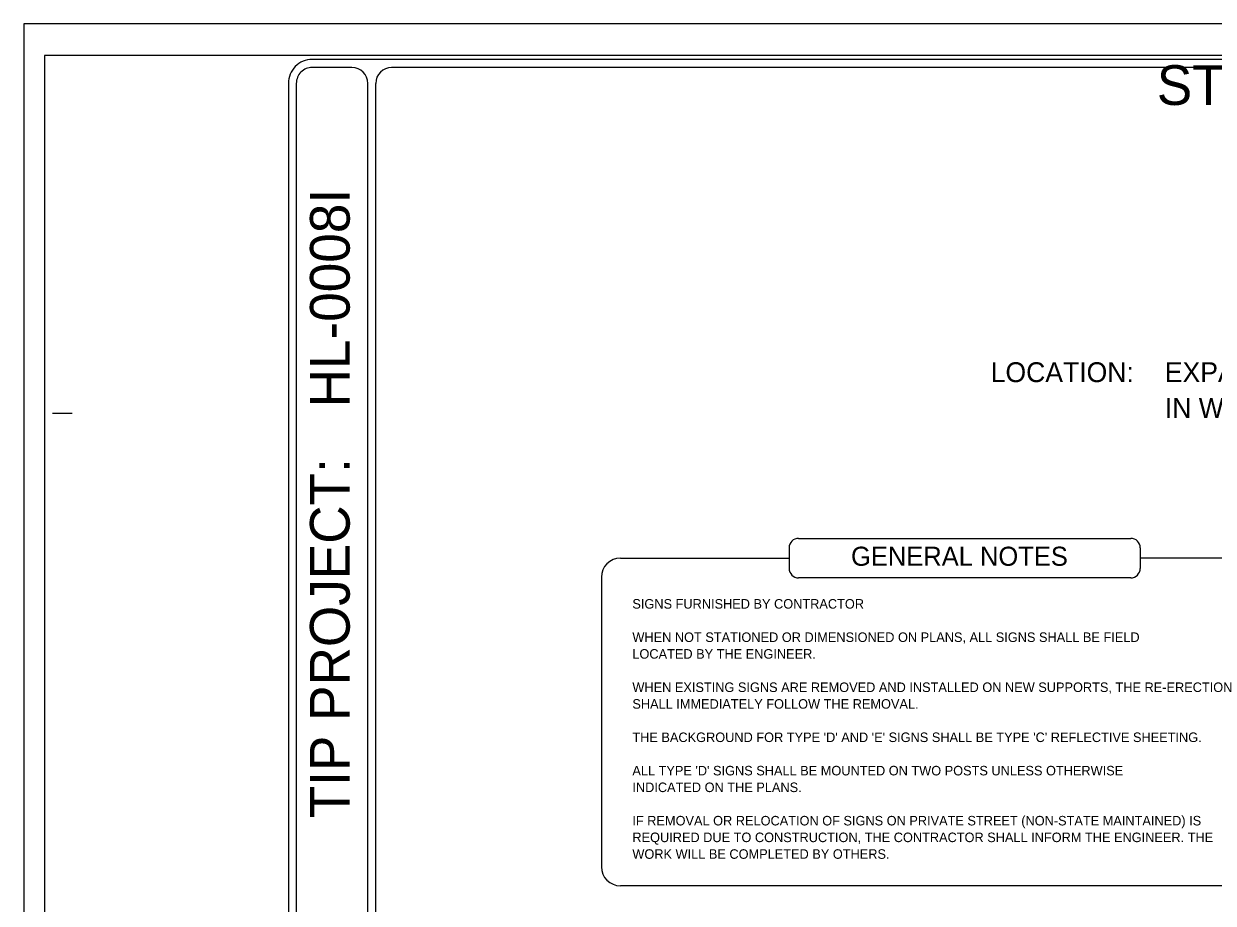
# Model space of a CAD drawing. Extents: x 2046816 to 2049224, y 578750 to 586986.
# Drawn here: x 2047541 to 2048289, y 586432 to 586986 of the extents above; entities that cross this region are included whole.
import ezdxf

# ---------------------------------------------------------------- set-up
doc = ezdxf.new("R2010")
doc.units = 0
for name, color, linetype in [('Default', 7, 'Continuous'), ('Sheet Data Field CELL', 7, 'Continuous'), ('Sheet Plot Border Inside CELL', 7, 'Continuous'), ('Sheet Plot Border Outside CELL', 7, 'Continuous'), ('Sheet Title CELL', 7, 'Continuous')]:
    doc.layers.add(name, color=color, linetype=linetype)

msp = doc.modelspace()

# ---------------------------------------------------------------- linework, layer by layer
at = {"layer": 'Sheet Plot Border Inside CELL'}
msp.add_lwpolyline([(2047553.67, 585910.81), (2049219.66, 585910.81), (2049219.66, 586965.81), (2047553.67, 586965.81)], close=True, dxfattribs=at)
at = {"layer": 'Sheet Plot Border Outside CELL'}
msp.add_lwpolyline([(2049224.17, 586985.81), (2047540.67, 586985.81), (2047540.67, 585890.81), (2049224.17, 585890.81)], close=True, dxfattribs=at)
at = {"layer": 'Sheet Title CELL'}
for p, q in [((2047757.16, 585928.33), (2047757.16, 586948.31)), ((2047762.16, 585928.31), (2047762.16, 586948.31)), ((2047558.66, 586740.81), (2047571.16, 586740.81)), ((2048028.31, 586661.97), (2048237.28, 586661.97)), ((2048022.31, 586655.97), (2048022.31, 586643.11)), ((2048243.28, 586655.97), (2048243.28, 586643.11)), ((2047916.15, 586649.54), (2048022.31, 586649.54)), ((2048349.44, 586649.54), (2048243.28, 586649.54)), ((2047904.15, 586637.54), (2047904.15, 586455.31)), ((2048237.28, 586637.11), (2048028.31, 586637.11)), ((2048349.44, 586443.31), (2047916.15, 586443.31))]:
    msp.add_line(p, q, dxfattribs=at)
for points in [[(2049192.16, 586963.31), (2047722.16, 586963.33)], [(2047747.17, 586958.31), (2047722.18, 586958.33)], [(2049192.16, 586958.31), (2047772.16, 586958.31)], [(2047707.16, 586948.33), (2047707.16, 585928.31)], [(2047712.18, 586948.33), (2047712.16, 585928.33)]]:
    msp.add_lwpolyline(points, dxfattribs=at)
for centre, radius, start, end in [((2047722.16, 586948.33), 15, 89.99952, 180), ((2047722.18, 586948.33), 10, 89.97135, 179.9993), ((2047747.16, 586948.31), 10, 0, 89.97135), ((2047772.16, 586948.31), 10, 90, 180), ((2048028.31, 586655.97), 6, 90, 180), ((2048237.28, 586655.97), 6, 360, 90), ((2047916.15, 586637.54), 12, 90, 180), ((2048028.31, 586643.11), 6, 180, 270), ((2048237.28, 586643.11), 6, 270, 0), ((2047916.15, 586455.31), 12, 180, 270)]:
    msp.add_arc(centre, radius, start, end, dxfattribs=at)

# ---------------------------------------------------------------- texts
at = {"layer": 'Default'}
for s, height, p in [('GENERAL NOTES', 12, (2048061.29, 586644.72)), ('SIGNS FURNISHED BY CONTRACTOR', 6, (2047923.67, 586617.76)), ('WHEN NOT STATIONED OR DIMENSIONED ON PLANS, ALL SIGNS SHALL BE FIELD ', 6, (2047923.67, 586596.77)), ('LOCATED BY THE ENGINEER.', 6, (2047923.67, 586586.27)), ('WHEN EXISTING SIGNS ARE REMOVED AND INSTALLED ON NEW SUPPORTS, THE RE-ERECTION', 6, (2047923.67, 586565.28)), ('SHALL IMMEDIATELY FOLLOW THE REMOVAL.', 6, (2047923.67, 586554.78)), ("THE BACKGROUND FOR TYPE 'D' AND 'E' SIGNS SHALL BE TYPE 'C' REFLECTIVE SHEETING.", 6, (2047923.67, 586533.79)), ("ALL TYPE 'D' SIGNS SHALL BE MOUNTED ON TWO POSTS UNLESS OTHERWISE", 6, (2047923.67, 586512.79)), ('INDICATED ON THE PLANS.', 6, (2047923.67, 586502.3)), ('IF REMOVAL OR RELOCATION OF SIGNS ON PRIVATE STREET (NON-STATE MAINTAINED) IS', 6, (2047923.67, 586481.3)), ('REQUIRED DUE TO CONSTRUCTION, THE CONTRACTOR SHALL INFORM THE ENGINEER. THE ', 6, (2047923.67, 586470.81)), ('WORK WILL BE COMPLETED BY OTHERS.', 6, (2047923.67, 586460.31))]:
    msp.add_text(s, height=height, dxfattribs=at).set_placement(p)
at = {"layer": 'Sheet Data Field CELL'}
for s, p in [('EXPAND THE ROADWAY FOR SR 2736 AND SR 1006', (2048258.75, 586760.3)), ('IN WAKE COUNTY SOUTH OF 540-EXTENSION', (2048258.75, 586737.8))]:
    msp.add_text(s, height=12.5001, rotation=360, dxfattribs=at).set_placement(p)
at = {"layer": 'Sheet Title CELL'}
for s, height, p in [('STATE OF NORTH CAROLINA', 24.9999, (2048253.72, 586934.73)), ('LOCATION: ', 12.5, (2048149.17, 586760.3))]:
    msp.add_text(s, height=height, dxfattribs=at).set_placement(p)
for s, p in [('HL-0008I', (2047745.78, 586744.38)), ('TIP PROJECT:', (2047745.78, 586485.81))]:
    msp.add_text(s, height=25, rotation=90, dxfattribs=at).set_placement(p)

doc.saveas('drawing.dxf')
